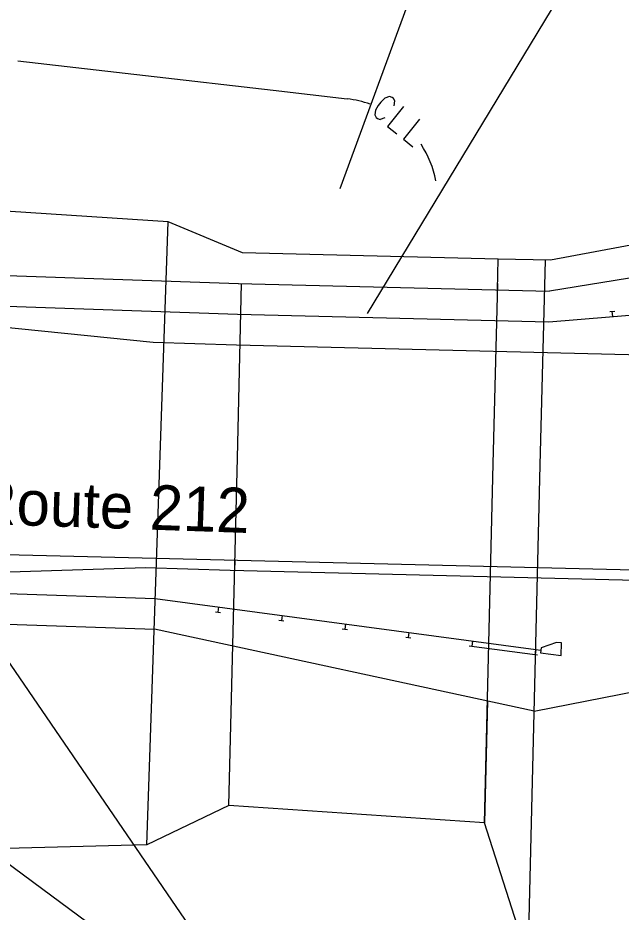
# Model space of a CAD drawing. Extents: x 2191309 to 2193046, y 863659 to 865133.
# Drawn here: x 2192726.5 to 2192785.4, y 863882.5 to 863969.7 of the extents above; entities that cross this region are included whole.
import ezdxf

# ---------------------------------------------------------------- set-up
doc = ezdxf.new("R2010")
doc.units = 0
for name, color, linetype in [('ANNOTATION', 7, 'Continuous'), ('D_Guardrail_Beam_Lt', 7, 'Continuous'), ('D_Guardrail_Beam_Rt', 7, 'Continuous'), ('D_Guardrail_End_MidSplice', 7, 'Continuous'), ('D_Roadway_Edge_Shoulder', 7, 'Continuous'), ('D_Roadway_Edge_TW', 7, 'Continuous'), ('D_Slope_ClearingLimitLine', 7, 'Continuous'), ('D_Slope_Direction', 7, 'Continuous'), ('D_Slope_Toe', 7, 'Continuous'), ('DIMENSIONS', 7, 'Continuous'), ('JUNK', 7, 'Continuous')]:
    doc.layers.add(name, color=color, linetype=linetype)

msp = doc.modelspace()

# ---------------------------------------------------------------- linework, layer by layer
at = {"layer": 'D_Guardrail_Beam_Lt'}
for p, q in [((2192718.973, 863941.795), (2192747.917, 863940.802)), ((2192747.917, 863940.802), (2192778.322, 863940.056))]:
    msp.add_line(p, q, dxfattribs=at)
at = {"layer": 'D_Guardrail_Beam_Rt'}
msp.add_line((2192718.012, 863913.812), (2192739.874, 863913.062), dxfattribs=at)
at = {"layer": 'D_Guardrail_End_MidSplice'}
for p, q in [((2192778.322, 863940.056), (2192815.694, 863943.14)), ((2192784.26, 863941.047), (2192784.758, 863941.089)), ((2192784.55, 863940.57), (2192784.509, 863941.068)), ((2192739.874, 863913.062), (2192777.042, 863908.077)), ((2192745.755, 863911.769), (2192746.25, 863911.702)), ((2192746.069, 863912.231), (2192746.003, 863911.735)), ((2192751.949, 863910.938), (2192752.445, 863910.871)), ((2192752.264, 863911.4), (2192752.197, 863910.905)), ((2192758.144, 863910.107), (2192758.639, 863910.041)), ((2192758.458, 863910.569), (2192758.392, 863910.074)), ((2192764.338, 863909.276), (2192764.834, 863909.21)), ((2192764.653, 863909.739), (2192764.586, 863909.243)), ((2192770.533, 863908.446), (2192777.223, 863907.549)), ((2192770.533, 863908.446), (2192771.029, 863908.379)), ((2192770.847, 863908.908), (2192770.781, 863908.413)), ((2192777.571, 863908.259), (2192777.504, 863907.763)), ((2192779.06, 863908.755), (2192777.571, 863908.259)), ((2192779.56, 863908.741), (2192779.06, 863908.755)), ((2192779.527, 863907.492), (2192779.56, 863908.741)), ((2192776.728, 863907.615), (2192777.223, 863907.549)), ((2192777.042, 863908.077), (2192776.975, 863907.582)), ((2192777.042, 863908.077), (2192777.537, 863908.011)), ((2192777.504, 863907.763), (2192779.527, 863907.492))]:
    msp.add_line(p, q, dxfattribs=at)
at = {"layer": 'D_Roadway_Edge_Shoulder'}
for p, q in [((2192815.842, 863949.138), (2192778.395, 863943.055)), ((2192690.012, 863945.791), (2192748.02, 863943.8)), ((2192747.99, 863943.801), (2192778.395, 863943.055)), ((2192747.649, 863916.801), (2192747.625, 863915.802)), ((2192688.846, 863911.811), (2192739.796, 863910.063)), ((2192776.883, 863902.08), (2192739.796, 863910.063))]:
    msp.add_line(p, q, dxfattribs=at)
for points in [[(2192747.828, 863937.803), (2192848.135, 863935.341), (2192873.144, 863935.409)], [(2192722.326, 863910.662), (2192722.558, 863917.417), (2192822.627, 863914.961), (2192822.472, 863908.633)], [(2192747.181, 863915.813), (2192847.595, 863913.347), (2192872.57, 863912.045)], [(2192776.883, 863902.08), (2192822.53, 863910.999), (2192857.623, 863910.073), (2192872.506, 863909.558)]]:
    msp.add_lwpolyline(points, dxfattribs=at)
at = {"layer": 'D_Roadway_Edge_TW'}
for points in [[(2192689.921, 863943.126), (2192739.666, 863938.083), (2192747.828, 863937.803)], [(2192688.938, 863914.476), (2192738.911, 863916.096), (2192747.181, 863915.813)]]:
    msp.add_lwpolyline(points, dxfattribs=at)
at = {"layer": 'D_Slope_ClearingLimitLine'}
for p, q in [((2192726.461, 863965.527), (2192751.394, 863962.646)), ((2192751.394, 863962.646), (2192758.633, 863961.809)), ((2192763.224, 863961.131), (2192763.285, 863961.607)), ((2192764.118, 863961.064), (2192762.554, 863959.114)), ((2192762.295, 863959.973), (2192761.835, 863959.808)), ((2192765.678, 863959.813), (2192764.114, 863957.863)), ((2192762.554, 863959.114), (2192763.464, 863958.384)), ((2192764.114, 863957.863), (2192765.024, 863957.133))]:
    msp.add_line(p, q, dxfattribs=at)
for points in [[(2192762.301, 863961.871), (2192761.911, 863961.5), (2192761.65, 863961.175), (2192761.373, 863960.713)], [(2192763.285, 863961.607), (2192763.143, 863961.847), (2192763.013, 863961.951), (2192762.757, 863962.031), (2192762.301, 863961.871)], [(2192761.373, 863960.713), (2192761.319, 863960.238), (2192761.449, 863959.999), (2192761.579, 863959.888), (2192761.835, 863959.808)]]:
    msp.add_lwpolyline(points, dxfattribs=at)
for start, end in [(70.19733, 83.40827), (11.23477, 33.42609)]:
    msp.add_arc((2192757.485, 863951.875), 10, start, end, dxfattribs=at)
at = {"layer": 'D_Slope_Direction'}
for p, q in [((2192773.305, 863943.18), (2192773.378, 863946.179)), ((2192772.32, 863903.062), (2192772.028, 863891.161))]:
    msp.add_line(p, q, dxfattribs=at)
at = {"layer": 'D_Slope_Toe'}
for points in [[(2192863.161, 863939.558), (2192844.233, 863944.544), (2192833.832, 863946.693), (2192823.463, 863949.007), (2192809.16, 863951.791), (2192778.469, 863946.054), (2192773.378, 863946.179), (2192748.386, 863946.792), (2192741.14, 863949.813), (2192723.71, 863950.964), (2192714.042, 863951.037)], [(2192872.45, 863907.143), (2192847.314, 863901.92), (2192832.609, 863896.877), (2192822.117, 863894.195), (2192814.437, 863891.936), (2192796.899, 863885.6), (2192776.3, 863877.861), (2192772.028, 863891.161), (2192747.062, 863892.868)], [(2192747.062, 863892.868), (2192739.054, 863889.015), (2192721.567, 863888.553), (2192720.247, 863888.374), (2192708.811, 863885.248)]]:
    msp.add_lwpolyline(points, dxfattribs=at)
at = {"layer": 'DIMENSIONS'}
msp.add_line((2192753.012, 863866.823), (2192697.244, 863948.19), dxfattribs=at)
for points in [[(2192784.274, 864011.047), (2192779.277, 864011.219), (2192757.914, 863953.042)], [(2192798.804, 863995.53), (2192793.807, 863995.701), (2192760.589, 863940.86)], [(2192758.009, 863866.651), (2192753.012, 863866.823), (2192695.557, 863909.317)]]:
    msp.add_lwpolyline(points, dxfattribs=at)
at = {"layer": 'JUNK'}
for p, q in [((2192740.359, 863927.053), (2192741.14, 863949.813)), ((2192777.484, 863926.072), (2192777.974, 863946.066)), ((2192747.895, 863926.798), (2192748.312, 863943.793)), ((2192772.887, 863926.185), (2192773.32, 863943.801)), ((2192739.054, 863889.015), (2192740.359, 863927.053)), ((2192747.062, 863892.868), (2192747.895, 863926.798)), ((2192772.028, 863891.161), (2192772.887, 863926.185)), ((2192776.3, 863877.861), (2192777.484, 863926.072))]:
    msp.add_line(p, q, dxfattribs=at)

# ---------------------------------------------------------------- texts
at = {"layer": 'ANNOTATION'}
msp.add_text('Route 212', height=4.375, rotation=358.03426, dxfattribs=at).set_placement((2192722.054, 863920.371))

doc.saveas('drawing.dxf')
